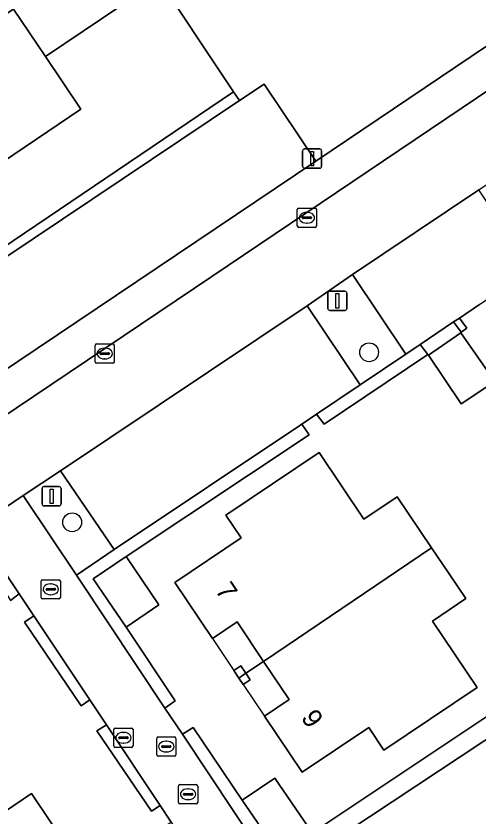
# Model space of a CAD drawing. Extents: x 158793 to 159888, y 384317 to 385256.
# Drawn here: x 159065.9 to 159089.95, y 384672.74 to 384714.36 of the extents above; entities that cross this region are included whole.
import ezdxf

# ---------------------------------------------------------------- set-up
doc = ezdxf.new("R2010")
doc.units = 0
for name, color, linetype in [('IMGEO_Boom', 7, 'Continuous'), ('IMGEO_Erf', 7, 'Continuous'), ('IMGEO_Groenvoorziening', 7, 'Continuous'), ('IMGEO_Haag', 7, 'Continuous'), ('IMGEO_Kolk', 7, 'Continuous'), ('IMGEO_Lichtmast', 7, 'Continuous'), ('IMGEO_Pand', 7, 'Continuous'), ('IMGEO_Pand_nummerreeks', 7, 'Continuous'), ('IMGEO_Pand_overbouw', 7, 'Continuous'), ('IMGEO_Parkeervlak_open', 7, 'Continuous'), ('IMGEO_Rijbaan_lokaal_open', 7, 'Continuous'), ('IMGEO_Rioolput', 7, 'Continuous'), ('IMGEO_Voetpad_open', 7, 'Continuous')]:
    doc.layers.add(name, color=color, linetype=linetype)

msp = doc.modelspace()

# ---------------------------------------------------------------- linework, layer by layer
at = {"layer": 'IMGEO_Boom'}
for centre in [(159084.284, 384696.863), (159068.824, 384688.021)]:
    msp.add_circle(centre, 0.489, dxfattribs=at)
at = {"layer": 'IMGEO_Erf'}
for points in [[(159062.098, 384700.196), (159077.226, 384710.406), (159064.307, 384729.784)], [(159064.307, 384729.784), (159077.226, 384710.406), (159077.535, 384709.955), (159078.815, 384710.81), (159081.517, 384706.804), (159095.282, 384716.103), (159097.641, 384717.699)], [(159063.917, 384721.019), (159066.215, 384722.559), (159071.358, 384714.886), (159067.435, 384712.248), (159069.284, 384709.519), (159062.879, 384705.201)], [(159090.039, 384699.358), (159088.983, 384698.647), (159089.373, 384698.126), (159089.084, 384697.911), (159088.685, 384698.446), (159086.937, 384697.269), (159087.334, 384696.743), (159081.945, 384693.125), (159081.548, 384693.65), (159080.775, 384693.133), (159081.167, 384692.563), (159071.631, 384686.237), (159073.342, 384683.726), (159071.628, 384682.562), (159074.194, 384678.736), (159073.658, 384678.352), (159074.561, 384676.996), (159075.131, 384677.353), (159077.683, 384673.558), (159079.38, 384674.71), (159081.117, 384672.177)], [(159081.247, 384671.812), (159096.708, 384682.114), (159098.87, 384679.188), (159107.236, 384684.664), (159107.906, 384683.665), (159108.91, 384684.374), (159108.265, 384685.338), (159115.197, 384689.875)], [(159050.27, 384651.45), (159074.221, 384667.534), (159072.476, 384670.066), (159074.163, 384671.229), (159073.534, 384672.147), (159073.98, 384672.417), (159073.399, 384673.289), (159072.96, 384673.002), (159070.111, 384677.172), (159070.61, 384677.479), (159069.74, 384678.786), (159069.295, 384678.477), (159066.351, 384682.826), (159066.834, 384683.149), (159066.072, 384684.293), (159065.616, 384683.953)], [(159063.169, 384671.525), (159066.706, 384673.907), (159068.755, 384670.864), (159066.839, 384669.588), (159068.38, 384667.283), (159066.732, 384666.186), (159067.531, 384664.99), (159062.795, 384661.825)]]:
    msp.add_lwpolyline(points, dxfattribs=at)
for points in [[(159089.083, 384694.179), (159087.375, 384696.714), (159089.064, 384697.872), (159090.833, 384695.347)], [(159087.527, 384686.698), (159088.416, 384685.384), (159089.317, 384684.051), (159087.588, 384682.885), (159089.91, 384679.42), (159085.055, 384676.166), (159084.264, 384677.346), (159080.808, 384675.019), (159078.843, 384677.94), (159080.122, 384678.8), (159078.786, 384680.785), (159077.407, 384682.834), (159076.123, 384681.972), (159074.164, 384684.892), (159077.618, 384687.206), (159076.82, 384688.397), (159081.68, 384691.649), (159084.008, 384688.189), (159085.737, 384689.344)], [(159077.867, 384680.164), (159078.093, 384679.83), (159077.732, 384679.587), (159077.507, 384679.92), (159077.245, 384680.308), (159077.606, 384680.551)]]:
    msp.add_lwpolyline(points, close=True, dxfattribs=at)
at = {"layer": 'IMGEO_Groenvoorziening'}
for points in [[(159077.535, 384709.955), (159077.226, 384710.406), (159062.098, 384700.196), (159061.974, 384700.381), (159060.277, 384699.25), (159058.584, 384701.789), (159054.673, 384707.426), (159054.255, 384708.058), (159053.877, 384707.82), (159054.304, 384707.184), (159060.196, 384698.421), (159062.192, 384699.702)], [(159083.423, 384700.904), (159081.061, 384699.284), (159083.813, 384695.166), (159086.192, 384696.768)], [(159088.983, 384698.647), (159088.685, 384698.446), (159089.084, 384697.911), (159089.373, 384698.126)], [(159087.334, 384696.743), (159086.937, 384697.269), (159086.192, 384696.768), (159083.813, 384695.166), (159081.548, 384693.65), (159081.945, 384693.125)], [(159071.631, 384686.237), (159081.167, 384692.563), (159080.775, 384693.133), (159071.015, 384686.602), (159069.058, 384685.263), (159069.154, 384685.121), (159073.658, 384678.352), (159074.194, 384678.736), (159071.628, 384682.562), (159069.919, 384685.072)], [(159068.226, 384690.7), (159066.28, 384689.406), (159066.372, 384689.264), (159069.058, 384685.263), (159071.015, 384686.602)], [(159063.869, 384687.602), (159063.78, 384687.735), (159057.782, 384683.689), (159047.185, 384676.54), (159047.504, 384676.068), (159061.91, 384685.784), (159063.603, 384686.937), (159065.322, 384684.416), (159065.616, 384683.953), (159066.072, 384684.293)], [(159066.834, 384683.149), (159066.351, 384682.826), (159069.295, 384678.477), (159069.74, 384678.786)], [(159070.61, 384677.479), (159070.111, 384677.172), (159072.96, 384673.002), (159073.399, 384673.289)]]:
    msp.add_lwpolyline(points, close=True, dxfattribs=at)
for points in [[(159099.356, 384678.075), (159107.906, 384683.665), (159107.236, 384684.664), (159098.87, 384679.188), (159096.708, 384682.114), (159081.247, 384671.812), (159081.043, 384672.126), (159079.424, 384671.023), (159077.683, 384673.558), (159075.131, 384677.353), (159074.561, 384676.996), (159078.61, 384670.91), (159078.571, 384670.884), (159078.783, 384670.563), (159079.482, 384669.508), (159096.312, 384680.64)], [(159097.742, 384678.578), (159096.312, 384680.64), (159079.482, 384669.508), (159079.569, 384669.376), (159079.588, 384669.39), (159080.687, 384667.744), (159085.364, 384670.862), (159087.614, 384667.53), (159092.976, 384659.587), (159114.386, 384674.002)]]:
    msp.add_lwpolyline(points, dxfattribs=at)
at = {"layer": 'IMGEO_Haag'}
for points in [[(159088.983, 384698.647), (159088.685, 384698.446), (159089.084, 384697.911), (159089.373, 384698.126)], [(159087.334, 384696.743), (159086.937, 384697.269), (159086.192, 384696.768), (159083.813, 384695.166), (159081.548, 384693.65), (159081.945, 384693.125)], [(159080.775, 384693.133), (159071.015, 384686.602), (159069.058, 384685.263), (159069.154, 384685.121), (159073.658, 384678.352), (159074.194, 384678.736), (159071.628, 384682.562), (159069.919, 384685.072), (159071.631, 384686.237), (159081.167, 384692.563)], [(159063.869, 384687.602), (159063.78, 384687.735), (159057.782, 384683.689), (159047.185, 384676.54), (159047.504, 384676.068), (159061.91, 384685.784), (159063.603, 384686.937), (159065.322, 384684.416), (159065.616, 384683.953), (159066.072, 384684.293)], [(159066.834, 384683.149), (159066.351, 384682.826), (159069.295, 384678.477), (159069.74, 384678.786)], [(159070.61, 384677.479), (159070.111, 384677.172), (159072.96, 384673.002), (159073.399, 384673.289)]]:
    msp.add_lwpolyline(points, close=True, dxfattribs=at)
msp.add_lwpolyline([(159099.356, 384678.075), (159107.906, 384683.665), (159107.236, 384684.664), (159098.87, 384679.188), (159096.708, 384682.114), (159081.247, 384671.812), (159081.043, 384672.126), (159079.424, 384671.023), (159077.683, 384673.558), (159075.131, 384677.353), (159074.561, 384676.996), (159078.61, 384670.91), (159078.571, 384670.884), (159078.783, 384670.563), (159079.482, 384669.508), (159096.312, 384680.64)], dxfattribs=at)
at = {"layer": 'IMGEO_Kolk'}
for p, q in [((159080.546, 384703.436), (159080.546, 384704.288)), ((159080.621, 384704.362), (159081.473, 384704.362)), ((159081.034, 384704.142), (159081.059, 384704.142)), ((159081.547, 384704.288), (159081.547, 384703.436)), ((159080.805, 384703.856), (159080.805, 384703.868)), ((159081.243, 384703.819), (159080.845, 384703.819)), ((159080.848, 384703.905), (159081.246, 384703.905)), ((159081.289, 384703.868), (159081.289, 384703.856)), ((159081.473, 384703.362), (159080.621, 384703.362)), ((159081.057, 384703.582), (159081.032, 384703.582)), ((159070.019, 384696.37), (159070.019, 384697.222)), ((159070.094, 384697.296), (159070.946, 384697.296)), ((159070.507, 384697.076), (159070.532, 384697.076)), ((159071.02, 384697.222), (159071.02, 384696.37)), ((159070.278, 384696.79), (159070.278, 384696.802)), ((159070.716, 384696.753), (159070.318, 384696.753)), ((159070.321, 384696.839), (159070.719, 384696.839)), ((159070.762, 384696.802), (159070.762, 384696.79)), ((159070.946, 384696.296), (159070.094, 384696.296)), ((159070.53, 384696.516), (159070.505, 384696.516)), ((159067.211, 384684.108), (159067.211, 384684.96)), ((159067.286, 384685.034), (159068.138, 384685.034)), ((159068.212, 384684.96), (159068.212, 384684.108)), ((159067.47, 384684.528), (159067.47, 384684.54)), ((159067.513, 384684.577), (159067.911, 384684.577)), ((159067.699, 384684.814), (159067.724, 384684.814)), ((159067.954, 384684.54), (159067.954, 384684.528)), ((159067.908, 384684.491), (159067.51, 384684.491)), ((159067.722, 384684.254), (159067.697, 384684.254)), ((159068.138, 384684.034), (159067.286, 384684.034)), ((159074.36, 384673.448), (159074.36, 384674.3)), ((159074.435, 384674.374), (159075.287, 384674.374)), ((159074.848, 384674.154), (159074.873, 384674.154)), ((159075.361, 384674.3), (159075.361, 384673.448)), ((159074.619, 384673.868), (159074.619, 384673.88)), ((159075.057, 384673.831), (159074.659, 384673.831)), ((159074.662, 384673.917), (159075.06, 384673.917)), ((159075.103, 384673.88), (159075.103, 384673.868)), ((159075.287, 384673.374), (159074.435, 384673.374)), ((159074.871, 384673.594), (159074.846, 384673.594))]:
    msp.add_line(p, q, dxfattribs=at)
for points in [[(159080.546, 384703.436), (159080.546, 384704.288)], [(159080.621, 384704.362), (159081.473, 384704.362)], [(159081.547, 384704.288), (159081.547, 384703.436)], [(159081.473, 384703.362), (159080.621, 384703.362)], [(159070.019, 384696.37), (159070.019, 384697.222)], [(159070.094, 384697.296), (159070.946, 384697.296)], [(159071.02, 384697.222), (159071.02, 384696.37)], [(159070.946, 384696.296), (159070.094, 384696.296)], [(159067.211, 384684.108), (159067.211, 384684.96)], [(159067.286, 384685.034), (159068.138, 384685.034)], [(159068.212, 384684.96), (159068.212, 384684.108)], [(159068.138, 384684.034), (159067.286, 384684.034)], [(159074.36, 384673.448), (159074.36, 384674.3)], [(159074.435, 384674.374), (159075.287, 384674.374)], [(159075.361, 384674.3), (159075.361, 384673.448)], [(159075.287, 384673.374), (159074.435, 384673.374)]]:
    msp.add_lwpolyline(points, dxfattribs=at)
for centre, radius, start, end in [((159080.623, 384704.286), 0.0765, 91.552, 178.448), ((159080.623, 384704.286), 0.0765, 91.552, 178.448), ((159081.471, 384704.286), 0.0765, 1.552, 88.448), ((159081.471, 384704.286), 0.0765, 1.552, 88.448), ((159080.845, 384703.865), 0.0403, 85.8775, 175.7526), ((159080.842, 384703.855), 0.0366, 178.938, 274.7102), ((159081.246, 384703.862), 0.043, 264.8664, 352.4533), ((159081.25, 384703.867), 0.0386, 1.7309, 96.639), ((159080.623, 384703.438), 0.0765, 181.552, 268.448), ((159080.623, 384703.438), 0.0765, 181.552, 268.448), ((159081.471, 384703.438), 0.0765, 271.552, 358.448), ((159081.471, 384703.438), 0.0765, 271.552, 358.448), ((159070.096, 384697.22), 0.0765, 91.552, 178.448), ((159070.096, 384697.22), 0.0765, 91.552, 178.448), ((159070.944, 384697.22), 0.0765, 1.552, 88.448), ((159070.944, 384697.22), 0.0765, 1.552, 88.448), ((159070.318, 384696.799), 0.0403, 85.8775, 175.7526), ((159070.315, 384696.789), 0.0366, 178.938, 274.7102), ((159070.719, 384696.796), 0.043, 264.8664, 352.4533), ((159070.723, 384696.801), 0.0386, 1.7309, 96.639), ((159070.096, 384696.372), 0.0765, 181.552, 268.448), ((159070.096, 384696.372), 0.0765, 181.552, 268.448), ((159070.944, 384696.372), 0.0765, 271.552, 358.448), ((159070.944, 384696.372), 0.0765, 271.552, 358.448), ((159067.288, 384684.958), 0.0765, 91.552, 178.448), ((159067.288, 384684.958), 0.0765, 91.552, 178.448), ((159068.136, 384684.958), 0.0765, 1.552, 88.448), ((159068.136, 384684.958), 0.0765, 1.552, 88.448), ((159067.51, 384684.537), 0.0403, 85.8775, 175.7526), ((159067.507, 384684.527), 0.0366, 178.938, 274.7102), ((159067.911, 384684.534), 0.043, 264.8664, 352.4533), ((159067.915, 384684.539), 0.0386, 1.7309, 96.639), ((159067.288, 384684.11), 0.0765, 181.552, 268.448), ((159067.288, 384684.11), 0.0765, 181.552, 268.448), ((159068.136, 384684.11), 0.0765, 271.552, 358.448), ((159068.136, 384684.11), 0.0765, 271.552, 358.448), ((159074.437, 384674.298), 0.0765, 91.552, 178.448), ((159074.437, 384674.298), 0.0765, 91.552, 178.448), ((159075.285, 384674.298), 0.0765, 1.552, 88.448), ((159075.285, 384674.298), 0.0765, 1.552, 88.448), ((159074.659, 384673.877), 0.0403, 85.8775, 175.7526), ((159074.656, 384673.867), 0.0366, 178.938, 274.7102), ((159075.06, 384673.874), 0.043, 264.8664, 352.4533), ((159075.064, 384673.879), 0.0386, 1.7309, 96.639), ((159074.437, 384673.45), 0.0765, 181.552, 268.448), ((159074.437, 384673.45), 0.0765, 181.552, 268.448), ((159075.285, 384673.45), 0.0765, 271.552, 358.448), ((159075.285, 384673.45), 0.0765, 271.552, 358.448)]:
    msp.add_arc(centre, radius, start, end, dxfattribs=at)
for centre, major_axis, ratio, start_param, end_param in [((159081.033, 384703.862), (-0.387, 0.002), 0.722429, 4.712389, 7.853982), ((159081.058, 384703.862), (-0.39, 0.002), 0.717154, 1.570796, 4.712389), ((159070.506, 384696.796), (-0.387, 0.002), 0.722429, 4.712389, 7.853982), ((159070.531, 384696.796), (-0.39, 0.002), 0.717154, 1.570796, 4.712389), ((159067.698, 384684.534), (-0.387, 0.002), 0.722429, 4.712389, 7.853982), ((159067.723, 384684.534), (-0.39, 0.002), 0.717154, 1.570796, 4.712389), ((159074.847, 384673.874), (-0.387, 0.002), 0.722429, 4.712389, 7.853982), ((159074.872, 384673.874), (-0.39, 0.002), 0.717154, 1.570796, 4.712389)]:
    msp.add_ellipse(centre, major_axis=major_axis, ratio=ratio, start_param=start_param, end_param=end_param, dxfattribs=at)
at = {"layer": 'IMGEO_Lichtmast'}
for p, q in [((159080.924, 384707.441), (159081.714, 384707.441)), ((159081.714, 384707.441), (159080.924, 384707.441)), ((159080.824, 384706.541), (159080.824, 384707.341)), ((159080.824, 384707.341), (159080.824, 384706.541)), ((159081.814, 384707.341), (159081.814, 384706.541)), ((159081.814, 384706.541), (159081.814, 384707.341)), ((159081.714, 384706.441), (159080.924, 384706.441)), ((159080.924, 384706.441), (159081.714, 384706.441)), ((159082.136, 384699.142), (159082.136, 384699.942)), ((159082.136, 384699.942), (159082.136, 384699.142)), ((159082.236, 384700.042), (159083.026, 384700.042)), ((159083.026, 384700.042), (159082.236, 384700.042)), ((159083.126, 384699.942), (159083.126, 384699.142)), ((159083.126, 384699.142), (159083.126, 384699.942)), ((159083.026, 384699.042), (159082.236, 384699.042)), ((159082.236, 384699.042), (159083.026, 384699.042)), ((159067.258, 384688.974), (159067.258, 384689.774)), ((159067.258, 384689.774), (159067.258, 384688.974)), ((159067.358, 384689.874), (159068.148, 384689.874)), ((159068.148, 384689.874), (159067.358, 384689.874)), ((159068.248, 384689.774), (159068.248, 384688.974)), ((159068.248, 384688.974), (159068.248, 384689.774)), ((159068.148, 384688.874), (159067.358, 384688.874)), ((159067.358, 384688.874), (159068.148, 384688.874))]:
    msp.add_line(p, q, dxfattribs=at)
for points in [[(159081.244, 384707.316), (159081.394, 384707.316), (159081.394, 384706.566), (159081.244, 384706.566), (159081.244, 384707.316)], [(159082.556, 384699.917), (159082.706, 384699.917), (159082.706, 384699.167), (159082.556, 384699.167), (159082.556, 384699.917)], [(159067.678, 384689.749), (159067.828, 384689.749), (159067.828, 384688.999), (159067.678, 384688.999), (159067.678, 384689.749)]]:
    msp.add_lwpolyline(points, dxfattribs=at)
for centre, start, end in [((159080.924, 384707.341), 90, 180), ((159080.924, 384707.341), 90, 180), ((159081.714, 384707.341), 0, 90), ((159081.714, 384707.341), 360, 90), ((159080.924, 384706.541), 180, 270), ((159080.924, 384706.541), 180, 270), ((159081.714, 384706.541), 270, 0), ((159081.714, 384706.541), 270, 0), ((159082.236, 384699.942), 90, 180), ((159082.236, 384699.942), 90, 180), ((159083.026, 384699.942), 0, 90), ((159083.026, 384699.942), 360, 90), ((159082.236, 384699.142), 180, 270), ((159082.236, 384699.142), 180, 270), ((159083.026, 384699.142), 270, 0), ((159083.026, 384699.142), 270, 0), ((159067.358, 384689.774), 90, 180), ((159067.358, 384689.774), 90, 180), ((159068.148, 384689.774), 0, 90), ((159068.148, 384689.774), 360, 90), ((159067.358, 384688.974), 180, 270), ((159067.358, 384688.974), 180, 270), ((159068.148, 384688.974), 270, 0), ((159068.148, 384688.974), 270, 0)]:
    msp.add_arc(centre, 0.1, start, end, dxfattribs=at)
at = {"layer": 'IMGEO_Pand'}
for points in [[(159066.215, 384722.559), (159063.917, 384721.019), (159062.093, 384723.742), (159060.41, 384722.616), (159064.036, 384717.265), (159059.282, 384714.126), (159060.128, 384712.846), (159060.973, 384711.565), (159065.765, 384714.713), (159067.435, 384712.248), (159071.358, 384714.886)], [(159067.435, 384712.248), (159065.765, 384714.713), (159060.973, 384711.565), (159057.405, 384709.221), (159059.441, 384706.194), (159061.361, 384707.489), (159062.879, 384705.201), (159069.284, 384709.519)], [(159087.375, 384696.714), (159089.083, 384694.179), (159090.833, 384695.347), (159089.064, 384697.872)], [(159087.527, 384686.698), (159085.737, 384689.344), (159084.008, 384688.189), (159081.68, 384691.649), (159076.82, 384688.397), (159077.618, 384687.206), (159074.164, 384684.892), (159076.123, 384681.972), (159077.407, 384682.834), (159078.786, 384680.785)], [(159087.588, 384682.885), (159089.317, 384684.051), (159088.416, 384685.384), (159087.527, 384686.698), (159078.786, 384680.785), (159080.122, 384678.8), (159078.843, 384677.94), (159080.808, 384675.019), (159084.264, 384677.346), (159085.055, 384676.166), (159089.91, 384679.42)], [(159069.919, 384685.072), (159071.628, 384682.562), (159073.342, 384683.726), (159071.631, 384686.237)], [(159077.606, 384680.551), (159077.245, 384680.308), (159077.507, 384679.92), (159077.867, 384680.164)], [(159077.867, 384680.164), (159077.507, 384679.92), (159077.732, 384679.587), (159078.093, 384679.83)], [(159079.38, 384674.71), (159077.683, 384673.558), (159079.424, 384671.023), (159081.043, 384672.126), (159081.117, 384672.177)], [(159066.839, 384669.588), (159068.755, 384670.864), (159066.706, 384673.907), (159063.169, 384671.525), (159058.429, 384668.333), (159060.167, 384665.758), (159062.795, 384661.825), (159067.531, 384664.99), (159066.732, 384666.186), (159068.38, 384667.283)]]:
    msp.add_lwpolyline(points, close=True, dxfattribs=at)
at = {"layer": 'IMGEO_Pand_overbouw'}
for points in [[(159077.507, 384679.92), (159077.867, 384680.164), (159078.786, 384680.785), (159077.407, 384682.834), (159076.123, 384681.972), (159077.245, 384680.308)], [(159078.786, 384680.785), (159077.867, 384680.164), (159077.507, 384679.92), (159077.732, 384679.587), (159078.843, 384677.94), (159080.122, 384678.8)]]:
    msp.add_lwpolyline(points, close=True, dxfattribs=at)
at = {"layer": 'IMGEO_Parkeervlak_open'}
for points in [[(159081.517, 384706.804), (159078.815, 384710.81), (159077.535, 384709.955), (159062.192, 384699.702), (159064.92, 384695.667)], [(159092.725, 384701.246), (159089.999, 384705.312), (159083.423, 384700.904), (159086.192, 384696.768), (159086.937, 384697.269), (159088.685, 384698.446), (159088.983, 384698.647), (159090.039, 384699.358), (159092.762, 384701.191)], [(159081.061, 384699.284), (159068.226, 384690.7), (159071.015, 384686.602), (159080.775, 384693.133), (159081.548, 384693.65), (159083.813, 384695.166)]]:
    msp.add_lwpolyline(points, close=True, dxfattribs=at)
at = {"layer": 'IMGEO_Rijbaan_lokaal_open'}
msp.add_lwpolyline([(159063.78, 384687.735), (159066.28, 384689.406), (159068.226, 384690.7), (159081.061, 384699.284), (159083.423, 384700.904), (159089.999, 384705.312), (159091.1, 384706.065), (159092.122, 384706.764), (159093.422, 384707.619), (159093.526, 384707.69), (159100.643, 384712.514), (159098.313, 384715.737), (159092.382, 384711.772), (159076.098, 384700.8), (159064.041, 384692.712)], dxfattribs=at)
at = {"layer": 'IMGEO_Rioolput'}
for p, q in [((159070.992, 384676.385), (159070.992, 384677.237)), ((159071.067, 384677.311), (159071.919, 384677.311)), ((159071.48, 384677.091), (159071.505, 384677.091)), ((159071.993, 384677.237), (159071.993, 384676.385)), ((159071.251, 384676.805), (159071.251, 384676.817)), ((159071.689, 384676.768), (159071.291, 384676.768)), ((159071.294, 384676.854), (159071.692, 384676.854)), ((159071.735, 384676.817), (159071.735, 384676.805)), ((159073.226, 384675.927), (159073.226, 384676.779)), ((159073.301, 384676.853), (159074.153, 384676.853)), ((159073.714, 384676.633), (159073.739, 384676.633)), ((159074.227, 384676.779), (159074.227, 384675.927)), ((159071.919, 384676.311), (159071.067, 384676.311)), ((159071.503, 384676.531), (159071.478, 384676.531)), ((159073.485, 384676.347), (159073.485, 384676.359)), ((159073.923, 384676.31), (159073.525, 384676.31)), ((159073.528, 384676.396), (159073.926, 384676.396)), ((159073.969, 384676.359), (159073.969, 384676.347)), ((159074.153, 384675.853), (159073.301, 384675.853)), ((159073.737, 384676.073), (159073.712, 384676.073))]:
    msp.add_line(p, q, dxfattribs=at)
for points in [[(159070.992, 384676.385), (159070.992, 384677.237)], [(159071.067, 384677.311), (159071.919, 384677.311)], [(159071.993, 384677.237), (159071.993, 384676.385)], [(159073.226, 384675.927), (159073.226, 384676.779)], [(159073.301, 384676.853), (159074.153, 384676.853)], [(159074.227, 384676.779), (159074.227, 384675.927)], [(159071.919, 384676.311), (159071.067, 384676.311)], [(159074.153, 384675.853), (159073.301, 384675.853)]]:
    msp.add_lwpolyline(points, dxfattribs=at)
for centre, radius, start, end in [((159071.069, 384677.235), 0.0765, 91.552, 178.448), ((159071.069, 384677.235), 0.0765, 91.552, 178.448), ((159071.917, 384677.235), 0.0765, 1.552, 88.448), ((159071.917, 384677.235), 0.0765, 1.552, 88.448), ((159071.291, 384676.814), 0.0403, 85.8775, 175.7526), ((159071.288, 384676.804), 0.0366, 178.938, 274.7102), ((159071.692, 384676.811), 0.043, 264.8664, 352.4533), ((159071.696, 384676.816), 0.0386, 1.7309, 96.639), ((159073.303, 384676.777), 0.0765, 91.552, 178.448), ((159073.303, 384676.777), 0.0765, 91.552, 178.448), ((159074.151, 384676.777), 0.0765, 1.552, 88.448), ((159074.151, 384676.777), 0.0765, 1.552, 88.448), ((159071.069, 384676.387), 0.0765, 181.552, 268.448), ((159071.069, 384676.387), 0.0765, 181.552, 268.448), ((159071.917, 384676.387), 0.0765, 271.552, 358.448), ((159071.917, 384676.387), 0.0765, 271.552, 358.448), ((159073.525, 384676.356), 0.0403, 85.8775, 175.7526), ((159073.522, 384676.346), 0.0366, 178.938, 274.7102), ((159073.926, 384676.353), 0.043, 264.8664, 352.4533), ((159073.93, 384676.358), 0.0386, 1.7309, 96.639), ((159073.303, 384675.929), 0.0765, 181.552, 268.448), ((159073.303, 384675.929), 0.0765, 181.552, 268.448), ((159074.151, 384675.929), 0.0765, 271.552, 358.448), ((159074.151, 384675.929), 0.0765, 271.552, 358.448)]:
    msp.add_arc(centre, radius, start, end, dxfattribs=at)
for centre, major_axis, ratio, start_param, end_param in [((159071.479, 384676.811), (-0.387, 0.002), 0.722429, 4.712389, 7.853982), ((159071.504, 384676.811), (-0.39, 0.002), 0.717154, 1.570796, 4.712389), ((159073.713, 384676.353), (-0.387, 0.002), 0.722429, 4.712389, 7.853982), ((159073.738, 384676.353), (-0.39, 0.002), 0.717154, 1.570796, 4.712389)]:
    msp.add_ellipse(centre, major_axis=major_axis, ratio=ratio, start_param=start_param, end_param=end_param, dxfattribs=at)
at = {"layer": 'IMGEO_Voetpad_open'}
for points in [[(159097.641, 384717.699), (159095.282, 384716.103), (159081.517, 384706.804), (159064.92, 384695.667), (159063.707, 384694.9), (159062.417, 384695.153), (159064.041, 384692.712), (159076.098, 384700.8)], [(159076.098, 384700.8), (159092.382, 384711.772), (159098.313, 384715.737), (159099.028, 384716.267)]]:
    msp.add_lwpolyline(points, dxfattribs=at)
msp.add_lwpolyline([(159069.154, 384685.121), (159069.058, 384685.263), (159066.372, 384689.264), (159066.28, 384689.406), (159063.78, 384687.735), (159063.869, 384687.602), (159066.072, 384684.293), (159066.834, 384683.149), (159069.74, 384678.786), (159070.61, 384677.479), (159073.399, 384673.289), (159073.98, 384672.417), (159076.087, 384669.252), (159078.571, 384670.884), (159078.61, 384670.91), (159074.561, 384676.996), (159073.658, 384678.352)], close=True, dxfattribs=at)

# ---------------------------------------------------------------- texts
at = {"layer": 'IMGEO_Pand_nummerreeks'}
for s, rotation, p in [('7', 303.8559, (159076.247, 384684.479)), ('9', 303.9304, (159080.713, 384677.848))]:
    msp.add_text(s, height=1, rotation=rotation, dxfattribs=at).set_placement(p)

doc.saveas('drawing.dxf')
